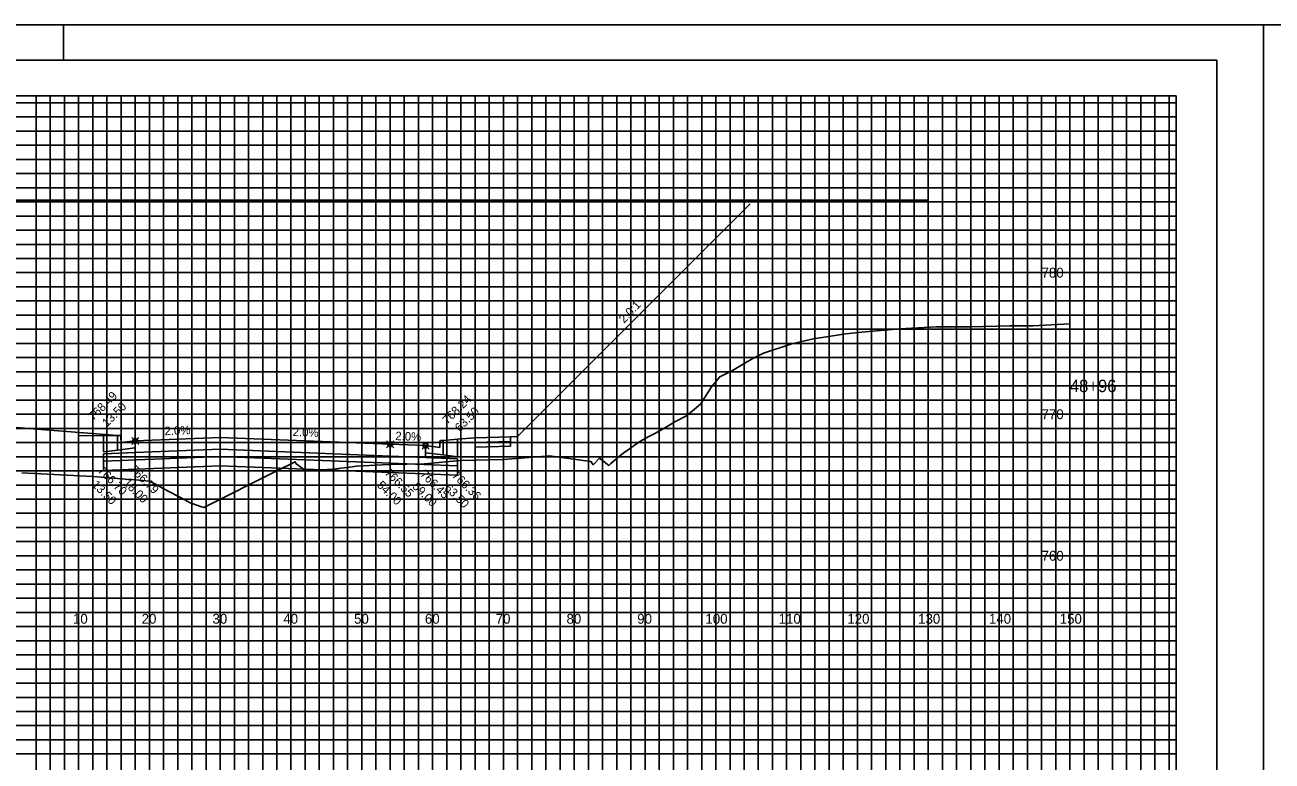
# Model space of a CAD drawing. Extents: x 578243 to 601557, y 174899 to 175559.
# Drawn here: x 600022.3 to 600198.4, y 175014.8 to 175118.8 of the extents above; entities that cross this region are included whole.
import ezdxf

# ---------------------------------------------------------------- set-up
doc = ezdxf.new("R2010")
doc.units = 0
for name, color, linetype in [('E_PROF_Grid', 7, 'Continuous'), ('E_PROF_GridMin', 7, 'Continuous'), ('P_CRDR_Label', 7, 'Continuous'), ('P_CRDR_Link', 7, 'Continuous'), ('P_E_XS_Ground', 7, 'Continuous'), ('P_RW_SlopeIntercepts', 7, 'Continuous'), ('P_XS_Text', 7, 'Continuous'), ('PLT_Sheet_Border', 7, 'Continuous'), ('PLT_Sheet_Info', 7, 'Continuous')]:
    doc.layers.add(name, color=color, linetype=linetype)

msp = doc.modelspace()

# ---------------------------------------------------------------- linework, layer by layer
at = {"layer": 'E_PROF_Grid'}
for p, q in [((600029.84, 174913.8), (600029.84, 175108.8)), ((600039.84, 174913.8), (600039.84, 175108.8)), ((600049.84, 174913.8), (600049.84, 175108.8)), ((600059.84, 174913.8), (600059.84, 175108.8)), ((600069.84, 174913.8), (600069.84, 175108.8)), ((600079.84, 174913.8), (600079.84, 175108.8)), ((600089.84, 174913.8), (600089.84, 175108.8)), ((600099.84, 174913.8), (600099.84, 175108.8)), ((600109.84, 174913.8), (600109.84, 175108.8)), ((600119.84, 174913.8), (600119.84, 175108.8)), ((600129.84, 174913.8), (600129.84, 175108.8)), ((600139.84, 174913.8), (600139.84, 175108.8)), ((600149.84, 174913.8), (600149.84, 175108.8)), ((600159.84, 174913.8), (600159.84, 175108.8)), ((600169.84, 174913.8), (600169.84, 175108.8)), ((600179.84, 174913.8), (600179.84, 175108.8)), ((599869.84, 175103.8), (600184.84, 175103.8)), ((599869.84, 175093.8), (600184.84, 175093.8)), ((599869.84, 175083.8), (600184.84, 175083.8)), ((599869.84, 175073.8), (600184.84, 175073.8)), ((599869.84, 175063.8), (600184.84, 175063.8)), ((599869.84, 175053.8), (600184.84, 175053.8)), ((599869.84, 175043.8), (600184.84, 175043.8)), ((599869.84, 175033.8), (600184.84, 175033.8)), ((599869.84, 175023.8), (600184.84, 175023.8))]:
    msp.add_line(p, q, dxfattribs=at)
at = {"layer": 'E_PROF_GridMin'}
for p, q in [((599869.84, 175107.8), (600184.84, 175107.8)), ((600023.84, 174913.8), (600023.84, 175108.8)), ((600025.84, 174913.8), (600025.84, 175108.8)), ((600027.84, 174913.8), (600027.84, 175108.8)), ((600031.84, 174913.8), (600031.84, 175108.8)), ((600033.84, 174913.8), (600033.84, 175108.8)), ((600035.84, 174913.8), (600035.84, 175108.8)), ((600037.84, 174913.8), (600037.84, 175108.8)), ((600041.84, 174913.8), (600041.84, 175108.8)), ((600043.84, 174913.8), (600043.84, 175108.8)), ((600045.84, 174913.8), (600045.84, 175108.8)), ((600047.84, 174913.8), (600047.84, 175108.8)), ((600051.84, 174913.8), (600051.84, 175108.8)), ((600053.84, 174913.8), (600053.84, 175108.8)), ((600055.84, 174913.8), (600055.84, 175108.8)), ((600057.84, 174913.8), (600057.84, 175108.8)), ((600061.84, 174913.8), (600061.84, 175108.8)), ((600063.84, 174913.8), (600063.84, 175108.8)), ((600065.84, 174913.8), (600065.84, 175108.8)), ((600067.84, 174913.8), (600067.84, 175108.8)), ((600071.84, 174913.8), (600071.84, 175108.8)), ((600073.84, 174913.8), (600073.84, 175108.8)), ((600075.84, 174913.8), (600075.84, 175108.8)), ((600077.84, 174913.8), (600077.84, 175108.8)), ((600081.84, 174913.8), (600081.84, 175108.8)), ((600083.84, 174913.8), (600083.84, 175108.8)), ((600085.84, 174913.8), (600085.84, 175108.8)), ((600087.84, 174913.8), (600087.84, 175108.8)), ((600091.84, 174913.8), (600091.84, 175108.8)), ((600093.84, 174913.8), (600093.84, 175108.8)), ((600095.84, 174913.8), (600095.84, 175108.8)), ((600097.84, 174913.8), (600097.84, 175108.8)), ((600101.84, 174913.8), (600101.84, 175108.8)), ((600103.84, 174913.8), (600103.84, 175108.8)), ((600105.84, 174913.8), (600105.84, 175108.8)), ((600107.84, 174913.8), (600107.84, 175108.8)), ((600111.84, 174913.8), (600111.84, 175108.8)), ((600113.84, 174913.8), (600113.84, 175108.8)), ((600115.84, 174913.8), (600115.84, 175108.8)), ((600117.84, 174913.8), (600117.84, 175108.8)), ((600121.84, 174913.8), (600121.84, 175108.8)), ((600123.84, 174913.8), (600123.84, 175108.8)), ((600125.84, 174913.8), (600125.84, 175108.8)), ((600127.84, 174913.8), (600127.84, 175108.8)), ((600131.84, 174913.8), (600131.84, 175108.8)), ((600133.84, 174913.8), (600133.84, 175108.8)), ((600135.84, 174913.8), (600135.84, 175108.8)), ((600137.84, 174913.8), (600137.84, 175108.8)), ((600141.84, 174913.8), (600141.84, 175108.8)), ((600143.84, 174913.8), (600143.84, 175108.8)), ((600145.84, 174913.8), (600145.84, 175108.8)), ((600147.84, 174913.8), (600147.84, 175108.8)), ((600151.84, 174913.8), (600151.84, 175108.8)), ((600153.84, 174913.8), (600153.84, 175108.8)), ((600155.84, 174913.8), (600155.84, 175108.8)), ((600157.84, 174913.8), (600157.84, 175108.8)), ((600161.84, 174913.8), (600161.84, 175108.8)), ((600163.84, 174913.8), (600163.84, 175108.8)), ((600165.84, 174913.8), (600165.84, 175108.8)), ((600167.84, 174913.8), (600167.84, 175108.8)), ((600171.84, 174913.8), (600171.84, 175108.8)), ((600173.84, 174913.8), (600173.84, 175108.8)), ((600175.84, 174913.8), (600175.84, 175108.8)), ((600177.84, 174913.8), (600177.84, 175108.8)), ((600181.84, 174913.8), (600181.84, 175108.8)), ((600183.84, 174913.8), (600183.84, 175108.8)), ((599869.84, 175105.8), (600184.84, 175105.8)), ((599869.84, 175101.8), (600184.84, 175101.8)), ((599869.84, 175099.8), (600184.84, 175099.8)), ((599869.84, 175097.8), (600184.84, 175097.8)), ((599869.84, 175095.8), (600184.84, 175095.8)), ((599869.84, 175091.8), (600184.84, 175091.8)), ((599869.84, 175089.8), (600184.84, 175089.8)), ((599869.84, 175087.8), (600184.84, 175087.8)), ((599869.84, 175085.8), (600184.84, 175085.8)), ((599869.84, 175081.8), (600184.84, 175081.8)), ((599869.84, 175079.8), (600184.84, 175079.8)), ((599869.84, 175077.8), (600184.84, 175077.8)), ((599869.84, 175075.8), (600184.84, 175075.8)), ((599869.84, 175071.8), (600184.84, 175071.8)), ((599869.84, 175069.8), (600184.84, 175069.8)), ((599869.84, 175067.8), (600184.84, 175067.8)), ((599869.84, 175065.8), (600184.84, 175065.8)), ((599869.84, 175061.8), (600184.84, 175061.8)), ((599869.84, 175059.8), (600184.84, 175059.8)), ((599869.84, 175057.8), (600184.84, 175057.8)), ((599869.84, 175055.8), (600184.84, 175055.8)), ((599869.84, 175051.8), (600184.84, 175051.8)), ((599869.84, 175049.8), (600184.84, 175049.8)), ((599869.84, 175047.8), (600184.84, 175047.8)), ((599869.84, 175045.8), (600184.84, 175045.8)), ((599869.84, 175041.8), (600184.84, 175041.8)), ((599869.84, 175039.8), (600184.84, 175039.8)), ((599869.84, 175037.8), (600184.84, 175037.8)), ((599869.84, 175035.8), (600184.84, 175035.8)), ((599869.84, 175031.8), (600184.84, 175031.8)), ((599869.84, 175029.8), (600184.84, 175029.8)), ((599869.84, 175027.8), (600184.84, 175027.8)), ((599869.84, 175025.8), (600184.84, 175025.8)), ((599869.84, 175021.8), (600184.84, 175021.8)), ((599869.84, 175019.8), (600184.84, 175019.8)), ((599869.84, 175017.8), (600184.84, 175017.8)), ((599869.84, 175015.8), (600184.84, 175015.8))]:
    msp.add_line(p, q, dxfattribs=at)
at = {"layer": 'P_CRDR_Label'}
for points in [[(600037.35, 175059.54), (600038.34, 175060.53)], [(600037.35, 175060.53), (600038.34, 175059.54)], [(600073.35, 175059.06), (600074.34, 175060.05)], [(600073.35, 175060.05), (600074.34, 175059.06)], [(600078.35, 175058.86), (600079.34, 175059.85)], [(600078.35, 175059.85), (600079.34, 175058.86)]]:
    msp.add_lwpolyline(points, dxfattribs=at)
for centre in [(600037.84, 175060.04), (600073.84, 175059.56), (600078.84, 175059.36)]:
    msp.add_circle(centre, 0.35, dxfattribs=at)
at = {"layer": 'P_CRDR_Link'}
msp.add_line((600124.69, 175093.5), (600091.84, 175060.65), dxfattribs=at)
for points in [[(600035.34, 175060.79), (600019.84, 175062.03)], [(600035.34, 175060.79), (600019.84, 175062.03)], [(600033.34, 175060.77), (600029.84, 175060.75)], [(600033.34, 175060.77), (600029.84, 175060.75)], [(600035.34, 175060.79), (600033.34, 175060.77)], [(600033.34, 175060.77), (600033.34, 175058.48)], [(600033.34, 175060.77), (600033.34, 175058.48)], [(600033.34, 175060.77), (600033.34, 175058.48)], [(600035.66, 175060.79), (600035.34, 175060.79)], [(600035.66, 175060.79), (600035.34, 175060.79)], [(600035.34, 175060.79), (600035.34, 175058.73)], [(600035.34, 175058.73), (600035.34, 175060.79)], [(600035.74, 175060.75), (600035.66, 175060.79)], [(600035.74, 175060.75), (600035.66, 175060.79)], [(600035.8, 175060.63), (600035.74, 175060.75)], [(600035.8, 175060.63), (600035.74, 175060.75)], [(600035.83, 175060.47), (600035.8, 175060.63)], [(600035.83, 175060.47), (600035.8, 175060.63)], [(600035.84, 175059.79), (600035.83, 175060.47)], [(600035.84, 175059.79), (600035.83, 175060.47)], [(600037.84, 175060.04), (600049.84, 175060.52)], [(600049.84, 175060.52), (600049.84, 175058.85)], [(600049.84, 175060.52), (600073.84, 175059.56)], [(600049.84, 175060.52), (600049.84, 175058.85)], [(600080.94, 175060.07), (600081.02, 175060.11)], [(600080.94, 175060.07), (600081.02, 175060.11)], [(600081.02, 175060.11), (600081.34, 175060.11)], [(600081.02, 175060.11), (600081.34, 175060.11)], [(600081.34, 175060.11), (600083.34, 175060.27)], [(600081.34, 175060.11), (600081.34, 175058.05)], [(600081.34, 175058.05), (600081.34, 175060.11)], [(600083.34, 175060.27), (600085.84, 175060.47)], [(600083.34, 175060.27), (600085.84, 175060.47)], [(600083.34, 175060.27), (600083.34, 175057.8)], [(600083.34, 175060.27), (600083.34, 175057.8)], [(600083.34, 175060.27), (600083.34, 175057.8)], [(600085.84, 175060.47), (600090.84, 175060.62)], [(600085.84, 175060.47), (600090.84, 175060.62)], [(600085.84, 175060.47), (600085.85, 175059.8)], [(600090.84, 175060.62), (600091.84, 175060.65)], [(600090.84, 175060.62), (600091.84, 175060.65)], [(600090.84, 175060.62), (600090.84, 175059.95)], [(600033.34, 175058.48), (600035.34, 175058.73)], [(600033.34, 175058.19), (600037.84, 175058.37)], [(600035.34, 175058.73), (600037.84, 175059.04)], [(600035.34, 175058.73), (600037.84, 175059.04)], [(600037.84, 175060.04), (600035.84, 175059.79)], [(600037.84, 175060.04), (600035.84, 175059.79)], [(600037.84, 175059.04), (600037.84, 175060.04)], [(600037.84, 175060.04), (600037.84, 175058.37)], [(600037.84, 175058.37), (600049.84, 175058.85)], [(600049.84, 175058.85), (600049.84, 175057.85)], [(600049.84, 175058.85), (600073.84, 175057.89)], [(600049.84, 175058.85), (600049.84, 175057.85)], [(600073.84, 175059.56), (600073.84, 175057.89)], [(600073.84, 175059.56), (600078.84, 175059.36)], [(600073.84, 175059.56), (600073.84, 175057.89)], [(600078.84, 175059.36), (600078.84, 175057.69)], [(600078.84, 175059.36), (600080.84, 175059.11)], [(600078.84, 175059.36), (600080.84, 175059.11)], [(600078.84, 175058.36), (600078.84, 175059.36)], [(600081.34, 175058.05), (600078.84, 175058.36)], [(600081.34, 175058.05), (600078.84, 175058.36)], [(600080.84, 175059.11), (600080.86, 175059.79)], [(600080.84, 175059.11), (600080.86, 175059.79)], [(600080.86, 175059.79), (600080.88, 175059.95)], [(600080.86, 175059.79), (600080.88, 175059.95)], [(600080.88, 175059.95), (600080.94, 175060.07)], [(600080.88, 175059.95), (600080.94, 175060.07)], [(600085.85, 175059.8), (600090.84, 175059.95)], [(600085.85, 175059.8), (600085.85, 175059.14)], [(600085.85, 175059.14), (600090.83, 175059.29)], [(600090.83, 175059.29), (600090.84, 175059.95)], [(600033.34, 175058.19), (600033.34, 175057.19)], [(600033.34, 175057.19), (600049.84, 175057.85)], [(600033.34, 175057.19), (600033.34, 175055.86)], [(600049.84, 175057.85), (600049.84, 175056.52)], [(600049.84, 175057.85), (600073.84, 175056.89)], [(600049.84, 175057.85), (600049.84, 175056.52)], [(600073.84, 175057.89), (600073.84, 175056.89)], [(600073.84, 175057.89), (600078.84, 175057.69)], [(600073.84, 175057.89), (600073.84, 175056.89)], [(600073.84, 175056.89), (600073.84, 175055.56)], [(600073.84, 175056.89), (600083.34, 175056.51)], [(600073.84, 175056.89), (600073.84, 175055.56)], [(600078.84, 175057.69), (600083.34, 175057.51)], [(600083.34, 175057.8), (600081.34, 175058.05)], [(600083.34, 175057.51), (600083.34, 175056.51)], [(600033.34, 175055.86), (600049.84, 175056.52)], [(600049.84, 175056.52), (600073.84, 175055.56)], [(600073.84, 175055.56), (600083.34, 175055.18)], [(600083.34, 175056.51), (600083.34, 175055.18)]]:
    msp.add_lwpolyline(points, dxfattribs=at)
at = {"layer": 'P_E_XS_Ground'}
msp.add_lwpolyline([(600021.82, 175055.53), (600031.84, 175055), (600036.02, 175054.66), (600036.84, 175054.6), (600037.34, 175054.56), (600039.84, 175054.36), (600041.06, 175053.71), (600041.34, 175053.55), (600041.79, 175053.31), (600041.8, 175053.3), (600044.83, 175051.69), (600045.49, 175051.31), (600046.92, 175050.83), (600047.53, 175050.63), (600057.95, 175055.84), (600060.43, 175057.08), (600060.57, 175056.78), (600061.74, 175055.94), (600062.55, 175055.85), (600065.73, 175056.02), (600068.14, 175056.32), (600069.1, 175056.44), (600073.69, 175056.69), (600078.7, 175056.81), (600083.73, 175057.27), (600089.83, 175057.42), (600094.02, 175057.72), (600096.37, 175057.92), (600102.13, 175057.11), (600102.25, 175057.06), (600102.52, 175056.66), (600103.42, 175057.58), (600104.73, 175056.56), (600104.85, 175056.69), (600105.03, 175056.85), (600106.52, 175058.11), (600106.53, 175058.12), (600109.12, 175059.96), (600110.37, 175060.65), (600111.41, 175061.18), (600112.98, 175062.08), (600113.94, 175062.66), (600115.7, 175063.58), (600117.69, 175065.2), (600119.23, 175067.65), (600120.4, 175069.1), (600122.21, 175069.96), (600124.96, 175071.61), (600126.58, 175072.43), (600130.56, 175073.76), (600133.65, 175074.46), (600138.21, 175075.14), (600140.94, 175075.45), (600145.84, 175075.86), (600150.96, 175076.14), (600155.79, 175076.14), (600161.37, 175076.27), (600164.64, 175076.29), (600169.84, 175076.57)], dxfattribs=at)
at = {"layer": 'P_RW_SlopeIntercepts'}
msp.add_line((599913.84, 175094.02), (600149.84, 175094.02), dxfattribs=at)
at = {"layer": 'PLT_Sheet_Border'}
for points in [[(599857.19, 174898.8), (600197.19, 174898.8), (600197.19, 175118.8), (599857.19, 175118.8)], [(600197.19, 174898.8), (600537.19, 174898.8), (600537.19, 175118.8), (600197.19, 175118.8)], [(599859.59, 174903.8), (600190.59, 174903.8), (600190.59, 175113.8), (599859.59, 175113.8)]]:
    msp.add_lwpolyline(points, close=True, dxfattribs=at)
at = {"layer": 'PLT_Sheet_Info'}
for p, q in [((600022.69, 175118.8), (600032.69, 175118.8)), ((600027.69, 175118.8), (600027.69, 175113.8)), ((600187.19, 175118.8), (600197.19, 175118.8)), ((600197.19, 175108.8), (600197.19, 175118.8)), ((600197.19, 175108.8), (600197.19, 175118.8)), ((600197.19, 175118.8), (600207.19, 175118.8)), ((599869.84, 175108.8), (600184.84, 175108.8)), ((600184.84, 174908.8), (600184.84, 175108.8))]:
    msp.add_line(p, q, dxfattribs=at)

# ---------------------------------------------------------------- texts
at = {"layer": 'P_CRDR_Label'}
for s, rotation, p in [('2.0:1', 46.711, (600106.89, 175076.57)), ('768.49', 45, (600031.93, 175062.82)), ('13.50', 45, (600033.87, 175061.93)), ('768.24', 45, (600081.93, 175062.31)), ('63.50', 45, (600083.69, 175061.25)), ('2.0%', 2.2906, (600042, 175060.83)), ('2.0%', 357.7094, (600060.05, 175060.73)), ('2.0%', 357.7094, (600074.55, 175060.15)), ('766.79', 315, (600036.99, 175055.9)), ('766.70', 315, (600032.49, 175055.72)), ('766.55', 315, (600072.99, 175055.42)), ('766.45', 315, (600077.99, 175055.22)), ('766.36', 315, (600082.49, 175055.04)), ('13.50', 315, (600031.64, 175053.74)), ('18.00', 315, (600036.08, 175053.98)), ('54.00', 315, (600071.9, 175053.68)), ('59.00', 315, (600076.89, 175053.49)), ('63.50', 315, (600081.43, 175053.27))]:
    msp.add_text(s, height=1.2, rotation=rotation, dxfattribs=at).set_placement(p)
at = {"layer": 'P_XS_Text'}
for s, height, p in [('780', 1.4, (600165.84, 175083.1)), ('48+96', 1.75, (600169.84, 175066.92)), ('770', 1.4, (600165.84, 175063.1)), ('760', 1.4, (600165.84, 175043.1)), ('10', 1.4, (600029.05, 175034.2)), ('20', 1.4, (600038.75, 175034.2)), ('30', 1.4, (600048.75, 175034.2)), ('40', 1.4, (600058.75, 175034.2)), ('50', 1.4, (600068.75, 175034.2)), ('60', 1.4, (600078.75, 175034.2)), ('70', 1.4, (600088.75, 175034.2)), ('80', 1.4, (600098.75, 175034.2)), ('90', 1.4, (600108.74, 175034.2)), ('100', 1.4, (600118.37, 175034.2)), ('110', 1.4, (600128.71, 175034.2)), ('120', 1.4, (600138.41, 175034.2)), ('130', 1.4, (600148.41, 175034.2)), ('140', 1.4, (600158.41, 175034.2)), ('150', 1.4, (600168.41, 175034.2))]:
    msp.add_text(s, height=height, rotation=360, dxfattribs=at).set_placement(p)

doc.saveas('drawing.dxf')
